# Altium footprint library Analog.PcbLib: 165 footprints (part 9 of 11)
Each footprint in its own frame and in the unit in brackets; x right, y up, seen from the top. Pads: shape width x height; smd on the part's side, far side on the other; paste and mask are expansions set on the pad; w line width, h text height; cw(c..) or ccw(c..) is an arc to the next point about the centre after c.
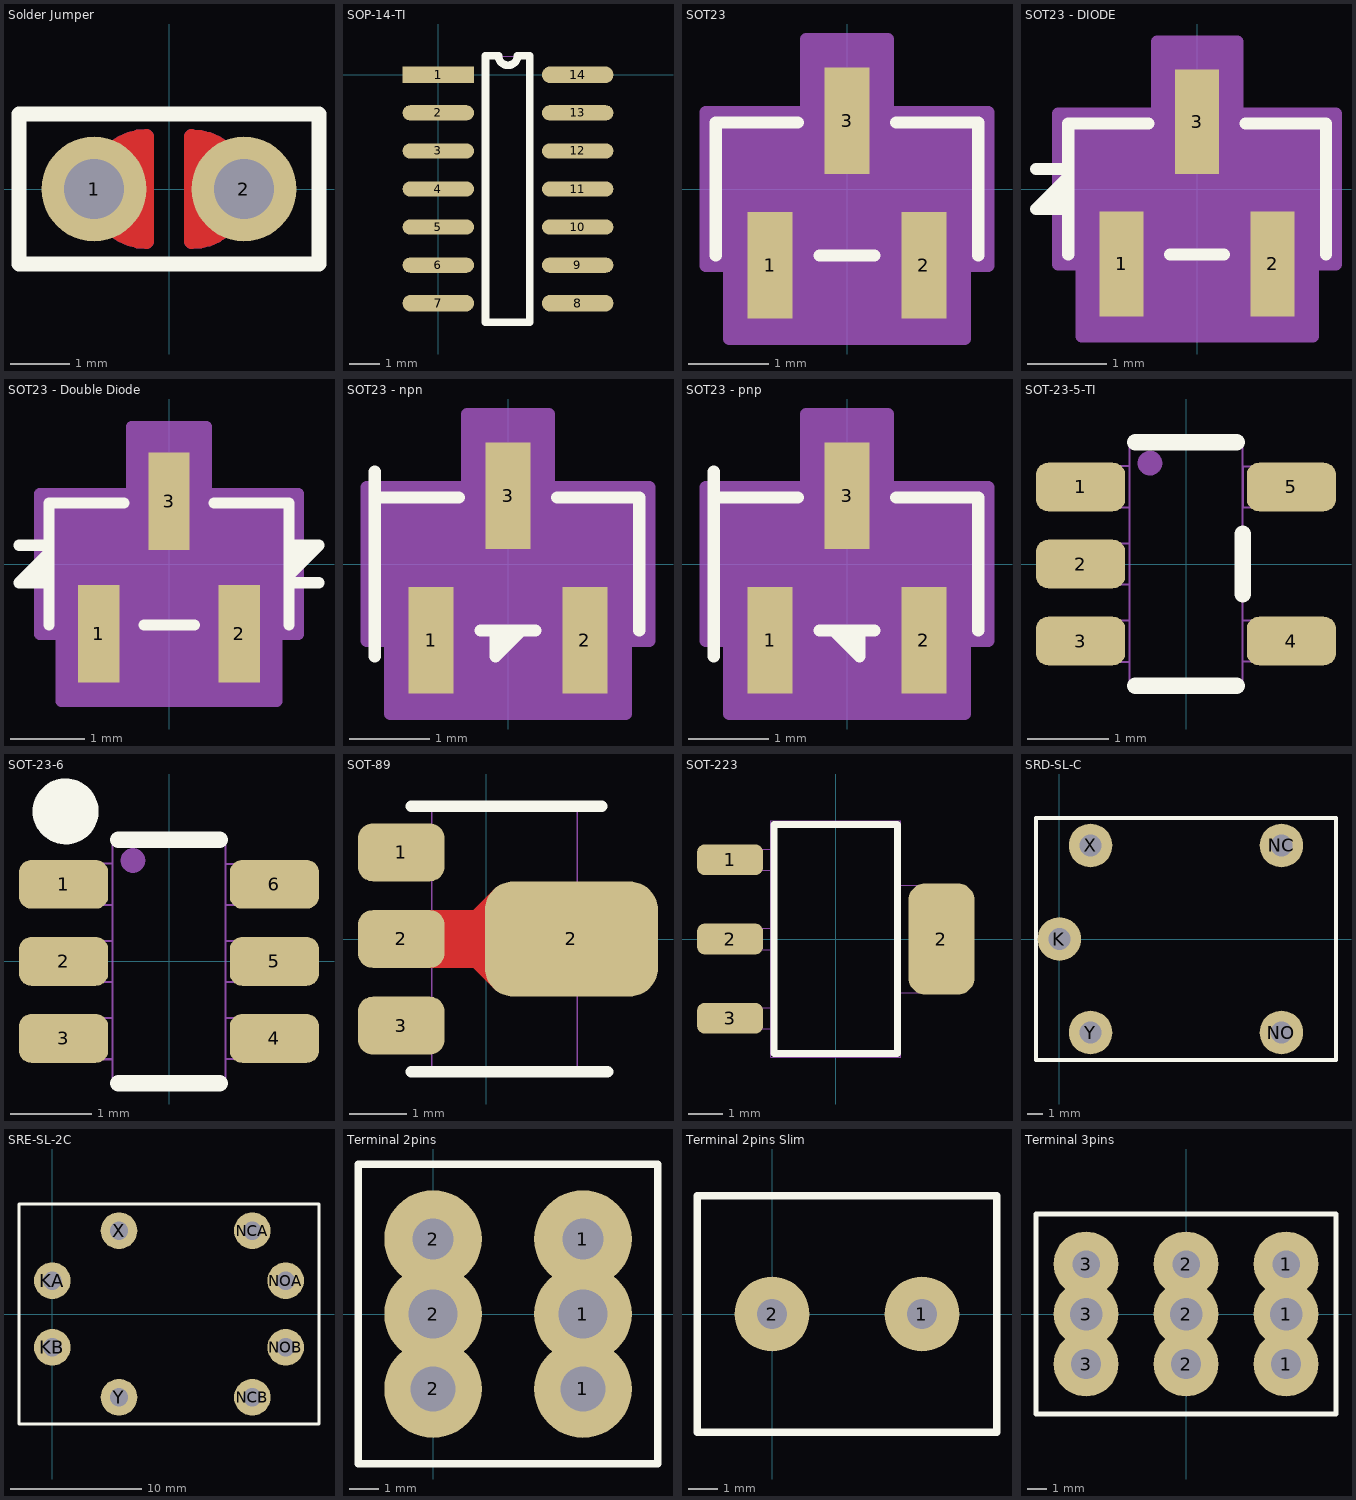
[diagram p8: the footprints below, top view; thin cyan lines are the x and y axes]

## Solder Jumper [mil]
pads (2):
  round 70 hole 40: 1(-50,0) 2(50,0)
Top Layer:
  region: 15,34.7 19.61,34.7 28.51,32.31 36.49,27.7 43.01,21.19 47.61,13.21 50,4.31 50,-4.91 47.61,-13.81 43.01,-21.79 36.49,-28.31 28.51,-32.92 19.61,-35.3 15,-35.3
  region: -15,-34.85 -19.61,-34.85 -28.51,-32.46 -36.49,-27.86 -43.01,-21.34 -47.61,-13.36 -50,-4.46 -50,4.76 -47.61,13.66 -43.01,21.64 -36.49,28.16 -28.51,32.77 -19.61,35.15 -15,35.15
  lines w10: -15,-35 cw(c-15,0) -15,35 -15,-35 ; 15,-35.15 ccw(c15,-0.15) 15,34.85 15,-35.15
Bottom Layer:
  region: 15,34.7 19.61,34.7 28.51,32.31 36.49,27.7 43.01,21.19 47.61,13.21 50,4.31 50,-4.91 47.61,-13.81 43.01,-21.79 36.49,-28.31 28.51,-32.92 19.61,-35.3 15,-35.3
  region: -15,-34.85 -19.61,-34.85 -28.51,-32.46 -36.49,-27.86 -43.01,-21.34 -47.61,-13.36 -50,-4.46 -50,4.76 -47.61,13.66 -43.01,21.64 -36.49,28.16 -28.51,32.77 -19.61,35.15 -15,35.15
  lines w10: -15,-35 cw(c-15,0) -15,35 -15,-35 ; 15,-35.15 ccw(c15,-0.15) 15,34.85 15,-35.15
Top Overlay:
  lines w10: -100,-50 100,-50 100,50 -100,50 -100,-50
Top Solder:
  rectangle: -10,-25 10,25
Bottom Solder:
  rectangle: -10,-25 10,25

## SOP-14-TI [mil]
pads (14):
  rect 94x22 smd: 1(0,0)
  oval 94x20 smd: 2(0,-50) 3(0,-100) 4(0,-150) 5(0,-200) 6(0,-250) 9(183,-250) 10(183,-200) 11(183,-150) 12(183,-100) 13(183,-50)
  oval 94x22 smd: 7(0,-300) 8(183,-300) 14(183,0)
Top Overlay:
  lines w10: 62,-325 120,-325 120,25 104,25 cw(c91.5,25) 79,25 62,25 62,-325
Mechanical 13:
  circle w10: c31.5,0 r4.92
  lines w1: 62.99,-323.82 62.99,24.61 120.08,24.61 120.08,-323.82 119.09,-324.8 63.98,-324.8 62.99,-323.82
  text ".Designator" at 74,-6 h40

## SOT23 [mil]
pads (3):
  rect 22x52 smd paste+0 mask+0: 1(-37.5,-37.21) 2(37.5,-37.21) 3(0,33.36)
Top Overlay:
  lines w6: -64,-32.5 -64,32.5 -24.1,32.5 ; -13.4,-32.5 13.4,-32.5 ; 24.1,32.5 64,32.5 64,-32.5
Mechanical 13:
  circle w0: c-49,-17.5 r5
  lines w1: -59,-27.5 59,-27.5 59,27.5 -59,27.5 -59,-27.5 ; -47.5,-49.21 -47.5,-27.5 -27.5,-27.5 -27.5,-49.21 -47.5,-49.21 ; -10,27.5 10,27.5 10,49.21 -10,49.21 -10,27.5 ; 27.5,-49.21 27.5,-27.5 47.5,-27.5 47.5,-49.21 27.5,-49.21
  text ".Designator" at -54,-14 h30
Mechanical 15:
  region: -69,-37.5 -69,37.5 -20,37.5 -20,73.21 20,73.21 20,37.5 69,37.5 69,-37.5 57.5,-37.5 57.5,-73.21 -57.5,-73.21 -57.5,-37.5
  region: 59,-27.5 -59,-27.5 -59,27.5 59,27.5
  lines w6: -69,-37.5 -69,37.5 -20,37.5 -20,73.21 20,73.21 20,37.5 69,37.5 69,-37.5 57.5,-37.5 57.5,-73.21 -57.5,-73.21 -57.5,-37.5 -69,-37.5

## SOT23 - DIODE [mil]
pads (3):
  rect 22x52 smd paste+0 mask+0: 1(-37.5,-37.21) 2(37.5,-37.21) 3(0,33.36)
Top Overlay:
  region: -64,-10 -64,6 -80,-10
  lines w6: -80,10 -64,10 ; -64,-32.5 -64,32.5 -24.1,32.5 ; -64,-10 -80,-10 -64,6 ; -13.4,-32.5 13.4,-32.5 ; 24.1,32.5 64,32.5 64,-32.5
Mechanical 13:
  circle w0: c-49,-17.5 r5
  lines w1: -59,-27.5 -59,27.5 59,27.5 59,-27.5 -59,-27.5 ; -47.5,-49.21 -27.5,-49.21 -27.5,-27.5 -47.5,-27.5 -47.5,-49.21 ; -10,27.5 -10,49.21 10,49.21 10,27.5 -10,27.5 ; 27.5,-49.21 47.5,-49.21 47.5,-27.5 27.5,-27.5 27.5,-49.21
  text ".Designator" at -54,-14 h30
Mechanical 15:
  region: 59,-27.5 -59,-27.5 -59,27.5 59,27.5
  region: -69,-37.5 -69,37.5 -20,37.5 -20,73.21 20,73.21 20,37.5 69,37.5 69,-37.5 57.5,-37.5 57.5,-73.21 -57.5,-73.21 -57.5,-37.5
  lines w6: -69,-37.5 -57.5,-37.5 -57.5,-73.21 57.5,-73.21 57.5,-37.5 69,-37.5 69,37.5 20,37.5 20,73.21 -20,73.21 -20,37.5 -69,37.5 -69,-37.5

## SOT23 - Double Diode [mil]
pads (3):
  rect 22x52 smd paste+0 mask+0: 1(-37.5,-37.21) 2(37.5,-37.21) 3(0,33.36)
Top Overlay:
  region: -64,-10 -64,6 -80,-10
  region: 64,10 64,-6 80,10
  lines w6: -80,10 -64,10 ; -64,-32.5 -64,32.5 -24.1,32.5 ; -64,-10 -80,-10 -64,6 ; -13.4,-32.5 13.4,-32.5 ; 24.1,32.5 64,32.5 64,-32.5 ; 64,-10 80,-10 ; 64,-6 80,10 64,10
Mechanical 13:
  circle w0: c-49,-17.5 r5
  lines w1: -59,-27.5 59,-27.5 59,27.5 -59,27.5 -59,-27.5 ; -47.5,-49.21 -47.5,-27.5 -27.5,-27.5 -27.5,-49.21 -47.5,-49.21 ; -10,27.5 10,27.5 10,49.21 -10,49.21 -10,27.5 ; 27.5,-49.21 27.5,-27.5 47.5,-27.5 47.5,-49.21 27.5,-49.21
  text ".Designator" at -54,-14 h30
Mechanical 15:
  region: -69,-37.5 -69,37.5 -20,37.5 -20,73.21 20,73.21 20,37.5 69,37.5 69,-37.5 57.5,-37.5 57.5,-73.21 -57.5,-73.21 -57.5,-37.5
  region: 59,-27.5 -59,-27.5 -59,27.5 59,27.5
  lines w6: -69,-37.5 -69,37.5 -20,37.5 -20,73.21 20,73.21 20,37.5 69,37.5 69,-37.5 57.5,-37.5 57.5,-73.21 -57.5,-73.21 -57.5,-37.5 -69,-37.5

## SOT23 - npn [mil]
pads (3):
  rect 22x52 smd paste+0 mask+0: 1(-37.5,-37.21) 2(37.5,-37.21) 3(0,33.36)
Top Overlay:
  region: -6.1,-32.6 6.3,-32.6 -6.1,-45
  lines w6: -65,-45 -65,45 ; -64,32.5 -24.1,32.5 ; -13.4,-32.5 13.4,-32.5 ; -6.1,-32.6 -6.1,-45 6.4,-32.5 ; 24.1,32.5 64,32.5 64,-32.5
Mechanical 13:
  circle w0: c-49,-17.5 r5
  lines w1: -59,-27.5 59,-27.5 59,27.5 -59,27.5 -59,-27.5 ; -47.5,-49.21 -47.5,-27.5 -27.5,-27.5 -27.5,-49.21 -47.5,-49.21 ; -10,27.5 10,27.5 10,49.21 -10,49.21 -10,27.5 ; 27.5,-49.21 27.5,-27.5 47.5,-27.5 47.5,-49.21 27.5,-49.21
  text ".Designator" at -54,-14 h30
Mechanical 15:
  region: -69,-37.5 -69,37.5 -20,37.5 -20,73.21 20,73.21 20,37.5 69,37.5 69,-37.5 57.5,-37.5 57.5,-73.21 -57.5,-73.21 -57.5,-37.5
  region: 59,-27.5 -59,-27.5 -59,27.5 59,27.5
  lines w6: -69,-37.5 -69,37.5 -20,37.5 -20,73.21 20,73.21 20,37.5 69,37.5 69,-37.5 57.5,-37.5 57.5,-73.21 -57.5,-73.21 -57.5,-37.5 -69,-37.5

## SOT23 - pnp [mil]
pads (3):
  rect 22x52 smd paste+0 mask+0: 1(-37.5,-37.21) 2(37.5,-37.21) 3(0,33.36)
Top Overlay:
  region: 6.1,-32.6 -6.3,-32.6 6.1,-45
  lines w6: -65,-45 -65,45 ; -64,32.5 -24.1,32.5 ; -13.4,-32.5 13.4,-32.5 ; -6.4,-32.5 6.1,-45 6.1,-32.6 ; 24.1,32.5 64,32.5 64,-32.5
Mechanical 13:
  circle w0: c-49,-17.5 r5
  lines w1: -59,-27.5 59,-27.5 59,27.5 -59,27.5 -59,-27.5 ; -47.5,-49.21 -47.5,-27.5 -27.5,-27.5 -27.5,-49.21 -47.5,-49.21 ; -10,27.5 10,27.5 10,49.21 -10,49.21 -10,27.5 ; 27.5,-49.21 27.5,-27.5 47.5,-27.5 47.5,-49.21 27.5,-49.21
  text ".Designator" at -54,-14 h30
Mechanical 15:
  region: -69,-37.5 -69,37.5 -20,37.5 -20,73.21 20,73.21 20,37.5 69,37.5 69,-37.5 57.5,-37.5 57.5,-73.21 -57.5,-73.21 -57.5,-37.5
  region: 59,-27.5 -59,-27.5 -59,27.5 59,27.5
  lines w6: -69,-37.5 -69,37.5 -20,37.5 -20,73.21 20,73.21 20,37.5 69,37.5 69,-37.5 57.5,-37.5 57.5,-73.21 -57.5,-73.21 -57.5,-37.5 -69,-37.5

## SOT-23-5-TI [mm]
pads (5):
  rrect50% 1.1x0.6 smd: 1(-1.3,0.95) 2(-1.3,0) 3(-1.3,-0.95) 4(1.3,-0.95) 5(1.3,0.95)
Top Overlay:
  lines w0.203: -0.625,-1.5 0.625,-1.5 ; -0.625,1.5 0.625,1.5 ; 0.7,-0.375 0.7,0.375
Mechanical 13:
  circle w0.152: c-0.445,1.245 r0.076
  lines w0.025: -1.25,-1.206 -0.699,-1.206 -0.699,-0.699 -1.25,-0.699 -1.25,-1.206 ; -1.25,-0.254 -1.25,0.254 -0.699,0.254 -0.699,-0.254 -1.25,-0.254 ; -1.25,0.699 -0.699,0.699 -0.699,1.206 -1.25,1.206 -1.25,0.699 ; -0.699,-1.499 0.699,-1.499 0.699,1.499 -0.699,1.499 -0.699,-1.499 ; 0.699,-1.204 0.699,-0.696 1.25,-0.696 1.25,-1.204 0.699,-1.204 ; 0.7,0.696 0.7,1.204 1.252,1.204 1.252,0.696 0.7,0.696
  text ".Designator" at -0.225,1.1 h0.76

## SOT-23-6 [mm]
height 1.5
pads (6):
  rrect50% 1.1x0.6 smd: 1(-1.3,0.95) 2(-1.3,0) 3(-1.3,-0.95) 4(1.3,-0.95) 5(1.3,0) 6(1.3,0.95)
Top Overlay:
  circle w0.406: c-1.275,1.85 r0.203
  lines w0.203: -0.625,-1.5 0.625,-1.5 ; -0.625,1.5 0.625,1.5
Mechanical 13:
  circle w0.152: c-0.445,1.245 r0.076
  lines w0.025: -0.699,-1.206 -1.25,-1.206 -1.25,-0.699 -0.699,-0.699 ; -0.699,-0.254 -1.25,-0.254 -1.25,0.254 -0.699,0.254 ; -0.699,0.699 -1.25,0.699 -1.25,1.206 -0.699,1.206 ; 0.699,-1.204 1.25,-1.204 1.25,-0.696 0.699,-0.696 ; 0.699,-0.254 1.25,-0.254 1.25,0.254 0.699,0.254 ; 0.7,0.696 1.252,0.696 1.252,1.204 0.7,1.204 ; -0.699,-1.499 0.699,-1.499 0.699,1.499 -0.699,1.499 -0.699,-1.499
  text ".Designator" at -0.225,1.1 h0.76

## SOT-89 [mm]
height 1.5
pads (4):
  rrect50% 1.5x1 smd: 1(-1.474,1.5) 2(-1.474,0) 3(-1.474,-1.5)
  rrect50% 3x2 smd: 2(1.474,0)
Top Layer:
  region: -1.026,0.5 -0.226,0.5 0.174,0.9 0.174,-0.9 -0.226,-0.5 -1.026,-0.5
Top Overlay:
  lines w0.203: -1.3,-2.3 2.1,-2.3 ; -1.3,2.3 2,2.3
Mechanical 13:
  lines w0.025: -0.95,-1.75 -2.05,-1.75 -2.05,-1.25 -0.95,-1.25 ; -0.95,-0.25 -2.05,-0.25 -2.05,0.25 -0.95,0.25 ; -0.95,1.25 -2.05,1.25 -2.05,1.75 -0.95,1.75 ; 1.575,-0.8 2.075,-0.8 2.075,0.8 1.575,0.8 ; -0.95,-2.3 1.575,-2.3 1.575,2.3 -0.95,2.3 -0.95,-2.3
  text ".Designator" at 0.2,2 h1.02

## SOT-223 [mil]
pads (4):
  rrect50% 75x35 smd: 1(-120,90) 2(-120,0) 3(-120,-90)
  rrect50% 75x126 smd: 2(120,0)
Top Overlay:
  lines w8: -70,-130 -70,130 70,130 70,-130 -70,-130
Mechanical 13:
  lines w1: -74,-102 -143,-102 -143,-78 -74,-78 ; -74,-12 -143,-12 -143,12 -74,12 ; -74,78 -143,78 -143,102 -74,102 ; 74,-61 143,-61 143,61 74,61 ; -74,-134 74,-134 74,134 -74,134 -74,-134
  text ".Designator" at -12,113 h40

## SRD-SL-C [mil] "Songle Relay 5pin"
height 622.05
pads (5):
  round 110 hole 55: K(0,0) NC(561.02,236.22) NO(561.02,-236.22) X(78.74,236.22) Y(78.74,-236.22)
Top Overlay:
  lines w10: -59.06,-305.12 698.82,-305.12 698.82,305.12 -59.06,305.12 -59.06,-305.12

## SRE-SL-2C [mil] "Songle Relay 8pin"
height 740.16
pads (8):
  round 110 hole 55: KA(0,100) KB(0,-100) NCA(600,250) NCB(600,-250) NOA(700,100) NOB(700,-100) X(200,250) Y(200,-250)
Top Overlay:
  lines w10: -100,-330 -100,330 800,330 800,-330 -100,-330

## Terminal 2pins [mil]
height 550
pads (6):
  round 130 hole 60: 1(200,-100) 2(0,-100)
  round 130 hole 65: 1(200,0) 2(0,0)
  round 130 hole 55: 1(200,100) 2(0,100)
Top Overlay:
  lines w10: -100,-200 -100,200 300,200 300,-200 -100,-200

## Terminal 2pins Slim [mil]
height 400
pads (2):
  round 100 hole 40: 1(200,0) 2(0,0)
Top Overlay:
  lines w10: -100,-157.48 -100,157.48 300,157.48 300,-157.48 -100,-157.48

## Terminal 3pins [mil]
height 550
pads (9):
  round 130 hole 60: 1(200,-100) 2(0,-100) 3(-200,-100)
  round 130 hole 65: 1(200,0) 2(0,0) 3(-200,0)
  round 130 hole 55: 1(200,100) 2(0,100) 3(-200,100)
Top Overlay:
  lines w10: -300,-200 300,-200 300,200 -300,200 -300,-200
